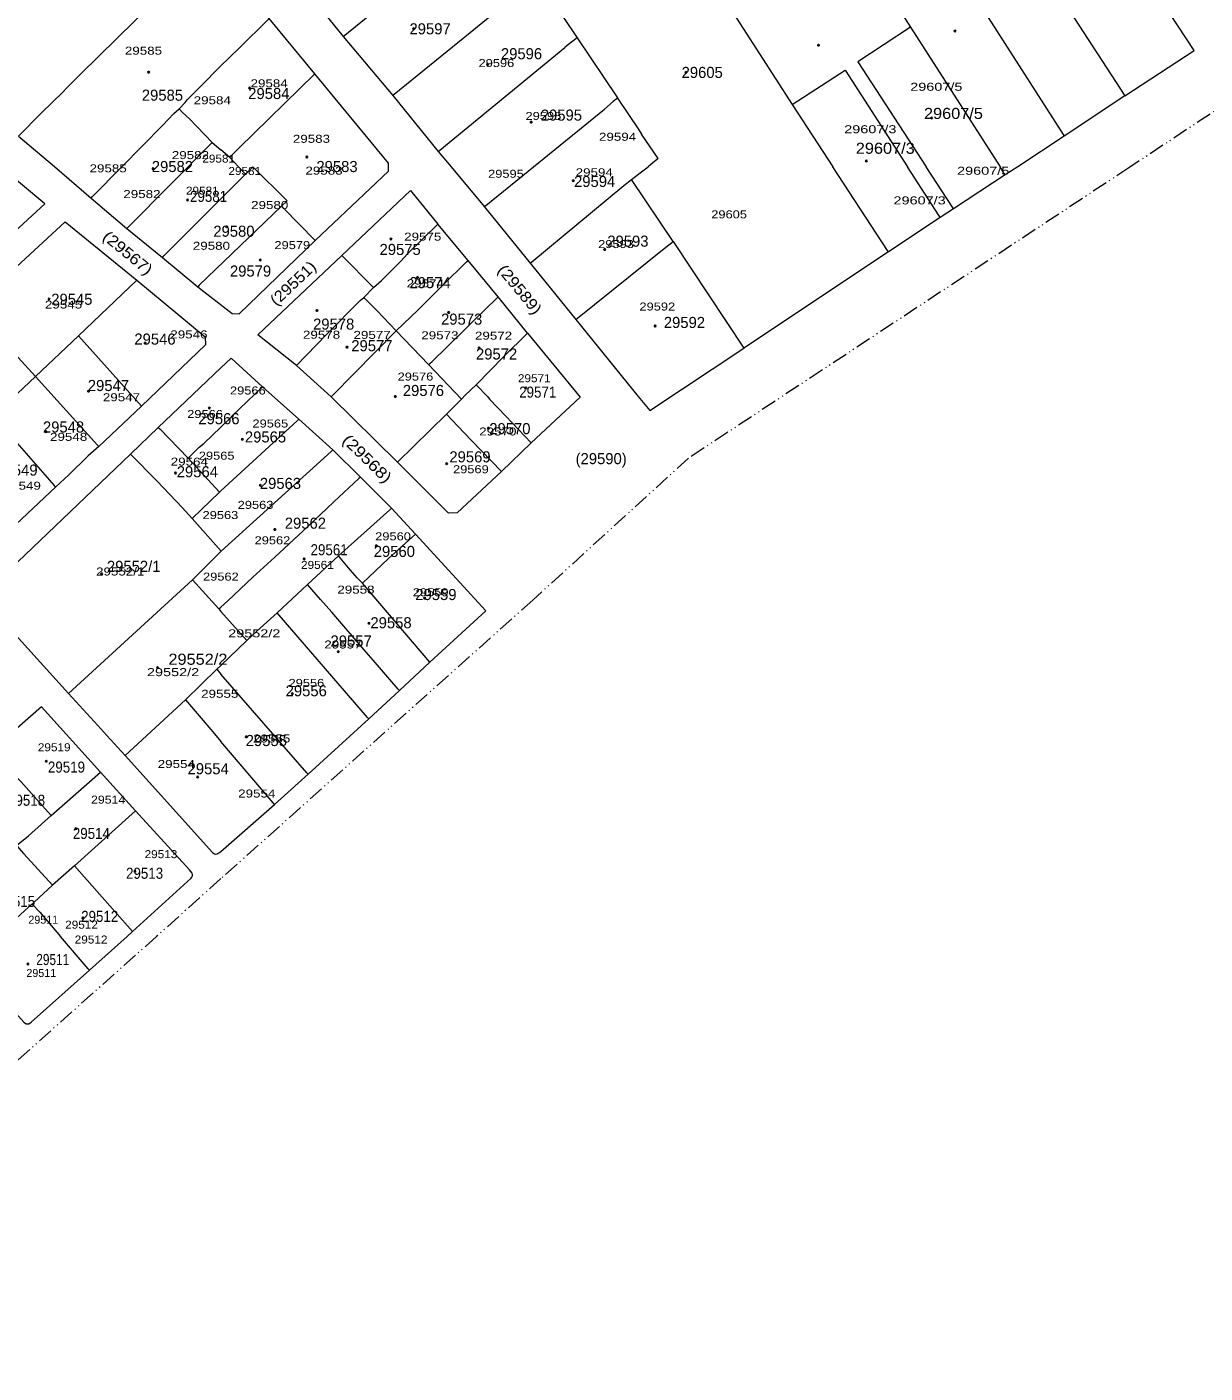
# Model space of a CAD drawing. Extents: x 650553 to 652508, y 239277 to 241647.
# Drawn here: x 651687 to 652069.7, y 240108.2 to 240545.4 of the extents above; entities that cross this region are included whole.
import ezdxf

# ---------------------------------------------------------------- set-up
doc = ezdxf.new("R2010")
doc.units = 0
doc.header["$PDMODE"] = 32
doc.header["$PDSIZE"] = 0.5
doc.linetypes.add('DASH_DOUBLE_DOT', pattern=[9.2, 5, -1.2, 0.3, -1.2, 0.3, -1.2])
for name, color, linetype in [('19', 7, 'Continuous'), ('20', 7, 'Continuous'), ('6', 7, 'Continuous')]:
    doc.layers.add(name, color=color, linetype=linetype)
for name, color, linetype, lineweight in [('3', 7, 'Continuous', 13), ('5', 7, 'Continuous', 13), ('52', 7, 'DASH_DOUBLE_DOT', 13)]:
    doc.layers.add(name, color=color, linetype=linetype, lineweight=lineweight)

msp = doc.modelspace()

# ---------------------------------------------------------------- linework, layer by layer
at = {"layer": '3'}
for p, q in [((651767.56, 240569.86), (651789.69, 240542.31)), ((652043.65, 240523), (652023.98, 240509.93)), ((651684.3, 240509.906), (651695.95, 240500.024)), ((651724.23, 240422.23), (651710.36, 240409.09)), ((651850.85, 240410.31), (651841.15, 240401)), ((651722.28, 240290.75), (651710.91, 240303.32)), ((651719.59, 240250), (651721.36, 240251.59))]:
    msp.add_line(p, q, dxfattribs=at)
for points in [[(651780.52, 240530.19), (651765.75, 240548.18), (651746.79, 240571.618), (651732.727, 240588.221)], [(652043.65, 240523), (652066.18, 240537.76), (652044.73, 240570.4)], [(651789.69, 240542.31), (651805.84, 240523.13), (651820.65, 240504.98)], [(651804.45, 240500), (651804.45, 240501.19), (651780.52, 240530.19)], [(652023.98, 240509.93), (652008.87, 240500), (652004.81, 240497.33), (651987.98, 240486.35), (651983.63, 240483.5), (651966.92, 240472.32), (651919.93, 240441.02)], [(651820.65, 240504.98), (651824.79, 240500), (651835.56, 240487.04), (651850.53, 240468.67), (651865.3, 240450.39), (651885.61, 240425.39)], [(651663.39, 240460.86), (651692.85, 240487.99), (651678.359, 240500.061)], [(651695.95, 240500.024), (651707.87, 240489.81), (651719.52, 240479.93), (651731.01, 240470.55), (651742.5, 240461.01)], [(651780.66, 240476.08), (651804.47, 240498.52), (651804.45, 240500)], [(651789.33, 240471.16), (651811.66, 240492.25), (651820.54, 240481.33)], [(651669.2, 240454.26), (651699.46, 240482.11), (651722.72, 240463.16)], [(651849.61, 240445.97), (651840.11, 240457.74), (651830.34, 240469.59), (651820.54, 240481.33)], [(651742.5, 240461.01), (651753.65, 240452.29), (651756.01, 240452.18), (651780.66, 240476.08)], [(651774.56, 240435.44), (651762.01, 240445.38), (651789.33, 240471.16)], [(651722.72, 240463.16), (651744.92, 240444.79), (651744.98, 240442.12), (651724.23, 240422.23)], [(651849.61, 240445.97), (651866.68, 240425.17), (651850.85, 240410.31)], [(651885.61, 240425.39), (651889.37, 240420.83), (651919.93, 240441.02)], [(651750, 240434.68), (651729.69, 240415.34), (651720.7, 240406.67)], [(651763.58, 240428.56), (651753.33, 240437.86), (651750, 240434.68)], [(651807.41, 240404.07), (651785.84, 240425.28), (651774.56, 240435.44)], [(651813.22, 240380.63), (651805.4, 240389.06), (651795.36, 240399.17), (651786.35, 240408), (651775.3, 240417.97), (651763.58, 240428.56)], [(651710.36, 240409.09), (651706.92, 240406.06), (651700.64, 240399.96), (651696.36, 240396.01), (651679.69, 240380.29)], [(651720.7, 240406.67), (651674.14, 240362.26), (651673.98, 240358.14), (651700.53, 240328.88)], [(651841.15, 240401), (651826.77, 240387.55), (651823.95, 240387.46), (651807.41, 240404.07)], [(651817.87, 240339.13), (651836.06, 240355.81), (651813.22, 240380.63)], [(651750, 240277.62), (651767.42, 240292.88), (651778.34, 240302.68), (651798.1, 240320.64), (651808.08, 240329.84), (651817.87, 240339.13)], [(651700.53, 240328.88), (651710.1, 240318.49), (651712.98, 240315.31), (651718.89, 240308.77)], [(651710.91, 240303.32), (651691.72, 240324.58), (651675.65, 240310.46)], [(651718.89, 240308.77), (651747.35, 240277.24), (651747.94, 240276.81), (651748.25, 240276.7), (651748.79, 240276.79), (651749.35, 240277.14), (651749.7, 240277.36), (651750, 240277.62)], [(651721.36, 240251.59), (651740.36, 240268.94), (651740.59, 240269.23), (651740.69, 240269.43), (651740.78, 240269.74), (651740.77, 240270.12), (651740.67, 240270.56), (651740.27, 240271.08), (651739.83, 240271.59), (651722.28, 240290.75)], [(651668.16, 240242.04), (651686.05, 240222.11), (651686.75, 240221.63), (651687.63, 240221.63), (651688.38, 240222.12), (651707.38, 240239.01), (651719.59, 240250)]]:
    msp.add_lwpolyline(points, dxfattribs=at)
at = {"layer": '5'}
for p, q in [((651952.88, 240578.32), (651974, 240545.35)), ((651789.69, 240542.31), (651814.44, 240562.63)), ((652022.45, 240555.62), (652043.65, 240523)), ((651974, 240545.35), (652003.1, 240500)), ((651865.79, 240541.92), (651878.88, 240522.33)), ((651878.854, 240522.308), (651885.76, 240512.02)), ((651851.53, 240500), (651874.65, 240518.75)), ((651885.76, 240512.02), (651886.65, 240510.58)), ((651892.03, 240502.7), (651886.65, 240510.58)), ((651752.92, 240503), (651750, 240505.47)), ((651752.92, 240503), (651755.74, 240500)), ((651865.3, 240450.39), (651894.58, 240473.92)), ((651896.95, 240475.71), (651919.93, 240441.02)), ((651703.75, 240445.08), (651722.72, 240463.16)), ((651740.68, 240385.76), (651750.108, 240375.13)), ((651749.33, 240356.36), (651750, 240356.95)), ((651758.4, 240346.09), (651750, 240355.59)), ((651748.66, 240336.76), (651750, 240335.23))]:
    msp.add_line(p, q, dxfattribs=at)
for points in [[(651973.9, 240588.07), (652023.66, 240510.43), (652023.98, 240509.93)], [(651903.75, 240569.66), (651935.56, 240520.19), (651948.78, 240500)], [(651684.3, 240509.906), (651691.776, 240517.523), (651698.788, 240524.311), (651699.785, 240525.447), (651704.534, 240530.177), (651722.068, 240547.369), (651727.626, 240552.993), (651733.93, 240559.128), (651737.908, 240563.103)], [(651831, 240543.63), (651833.38, 240545.52), (651846.72, 240556.46), (651852.61, 240561.44), (651865.79, 240541.92), (651862.49, 240539.35), (651861.77, 240538.68)], [(651765.75, 240548.18), (651765.25, 240547.685), (651756.07, 240538.6), (651749.902, 240532.663)], [(651974, 240545.35), (651956.96, 240534.09), (651979.11, 240500)], [(651805.84, 240523.13), (651806.34, 240523.537), (651831, 240543.63)], [(651820.65, 240504.98), (651821.15, 240505.39), (651861.77, 240538.68)], [(651717.88, 240500), (651731.008, 240513.379), (651734.733, 240517.238), (651736.464, 240518.811), (651738.371, 240520.83), (651739.09, 240521.71), (651743.385, 240526.043), (651749.902, 240532.663)], [(651935.56, 240520.19), (651952.8, 240531.41), (651973.01, 240500)], [(651752.92, 240503), (651753.24, 240503.39), (651755.87, 240506.04), (651780.52, 240530.19)], [(651878.88, 240522.33), (651878.854, 240522.308), (651877.48, 240521.15), (651874.65, 240518.75)], [(651736.464, 240518.811), (651737.589, 240517.572), (651739.81, 240515.514), (651747.169, 240507.868), (651750, 240505.47)], [(651719.52, 240479.93), (651720.015, 240480.43), (651747.169, 240507.868)], [(651707.87, 240489.81), (651708.361, 240490.31), (651717.88, 240500)], [(651758.04, 240497.55), (651757.571, 240498.05), (651755.74, 240500)], [(651758.04, 240497.55), (651760.36, 240499.99), (651771.6, 240488.91), (651769.76, 240487.19)], [(651835.56, 240487.04), (651836.06, 240487.446), (651851.53, 240500)], [(651850.53, 240468.67), (651851.03, 240469.086), (651880.9, 240493.93), (651883.43, 240495.82), (651885.76, 240497.68), (651888.76, 240500)], [(651892.03, 240502.7), (651889.55, 240500.61), (651888.76, 240500)], [(651966.92, 240472.32), (651966.592, 240472.82), (651948.78, 240500)], [(651983.63, 240483.5), (651983.308, 240484), (651973.01, 240500)], [(651987.98, 240486.35), (651987.655, 240486.85), (651979.11, 240500)], [(652004.81, 240497.33), (652004.49, 240497.83), (652003.1, 240500)], [(651731.01, 240470.55), (651731.51, 240471.049), (651758.04, 240497.55)], [(651894.58, 240473.92), (651896.95, 240475.71), (651883.43, 240495.82)], [(651769.76, 240487.19), (651743, 240461.49), (651742.5, 240461.01)], [(651769.76, 240487.19), (651770.251, 240486.69), (651780.66, 240476.08)], [(651799.55, 240460.76), (651802.16, 240463.02), (651802.86, 240463.74), (651808.5, 240469.28), (651810.61, 240471.69), (651820.54, 240481.33)], [(651774.56, 240435.44), (651784.33, 240445.56), (651795.26, 240456.54), (651796.45, 240457.5), (651799.55, 240460.76), (651789.33, 240471.16)], [(651822.16, 240461.55), (651829.84, 240469.099), (651830.34, 240469.59)], [(651806.92, 240446.7), (651814.06, 240453.48), (651819.13, 240458.47), (651822.16, 240461.55)], [(651785.84, 240425.28), (651786.332, 240425.78), (651806.92, 240446.7), (651800.82, 240453.17), (651796.45, 240457.5)], [(651831.81, 240449.76), (651839.61, 240457.259), (651840.11, 240457.74)], [(651669.2, 240454.26), (651689.84, 240431.91), (651676.1, 240418.98)], [(651817.47, 240435.75), (651818.5, 240436.62), (651829.03, 240446.97), (651831.81, 240449.76)], [(651689.84, 240431.91), (651703.75, 240445.08), (651724.23, 240422.23)], [(651807.41, 240404.07), (651823.29, 240419.61), (651828.2, 240424.54), (651817.47, 240435.75), (651806.92, 240446.7)], [(651828.2, 240424.54), (651829.4, 240425.82), (651832.9, 240429.2), (651837.5, 240433.81), (651841.84, 240438.26), (651849.61, 240445.97)], [(651689.84, 240431.91), (651709.91, 240409.59), (651710.36, 240409.09)], [(651763.58, 240428.56), (651753.53, 240418.94), (651753.16, 240418.47), (651750, 240415.45)], [(651832.9, 240429.2), (651836.72, 240425.27), (651837.32, 240424.47), (651842.59, 240418.97), (651850.85, 240410.31)], [(651676.1, 240418.98), (651695.919, 240396.51), (651696.36, 240396.01)], [(651775.3, 240417.97), (651774.8, 240417.51), (651750, 240394.7)], [(651823.29, 240419.61), (651826.98, 240415.73), (651831.47, 240411.08), (651841.15, 240401)], [(651729.69, 240415.34), (651730.177, 240414.84), (651739.42, 240405.35), (651749.62, 240394.35), (651750, 240394.7)], [(651739.42, 240405.35), (651742.95, 240408.96), (651744.45, 240410.16), (651750, 240415.45)], [(651720.7, 240406.67), (651729.37, 240397.82), (651737.47, 240389.28), (651740.68, 240385.76), (651749.62, 240394.35)], [(651786.35, 240408), (651785.85, 240407.547), (651750.108, 240375.13)], [(651795.36, 240399.17), (651794.86, 240398.71), (651786.67, 240391.17), (651784.48, 240389.04), (651776.76, 240381.76), (651767.59, 240373.22), (651760.41, 240366.68), (651752.33, 240359.03), (651750, 240356.95)], [(651805.4, 240389.06), (651804.9, 240388.609), (651788.24, 240373.59), (651778.18, 240364.32), (651768.32, 240355.07), (651761.69, 240349.11), (651758.4, 240346.09), (651750, 240338.04)], [(651817.87, 240339.13), (651795.98, 240364.7), (651804.49, 240372.71), (651813.22, 240380.63)], [(651700.53, 240328.88), (651740.82, 240365.88), (651750.108, 240375.13)], [(651795.98, 240364.7), (651794.3, 240366.52), (651792.14, 240368.99), (651791.45, 240369.7), (651788.24, 240373.59)], [(651740.82, 240365.88), (651749.33, 240356.36), (651750, 240355.59)], [(651808.08, 240329.84), (651807.643, 240330.34), (651799.44, 240339.72), (651797.23, 240342.29), (651786.04, 240355.28), (651782.4, 240359.43), (651778.18, 240364.32)], [(651798.1, 240320.64), (651797.668, 240321.14), (651768.32, 240355.07)], [(651718.89, 240308.77), (651738.52, 240326.9), (651748.66, 240336.76), (651750, 240338.04)], [(651778.34, 240302.68), (651777.905, 240303.18), (651750, 240335.23)], [(651738.52, 240326.9), (651747.42, 240316.41), (651750, 240313.37)], [(651767.42, 240292.88), (651766.995, 240293.38), (651750, 240313.37)], [(651675.65, 240310.46), (651684.01, 240301.45), (651685.08, 240300.35), (651690.2, 240294.5), (651694.89, 240289.25), (651710.91, 240303.32)], [(651722.28, 240290.75), (651702.45, 240272.91), (651721.36, 240251.59)], [(651683.68, 240279.53), (651687.51, 240282.73), (651694.89, 240289.25)], [(651683.68, 240279.53), (651686.05, 240276.8), (651695.36, 240266.66)], [(651702.45, 240272.91), (651695.36, 240266.66), (651689.41, 240261.12)], [(651689.41, 240261.12), (651688.7, 240260.49), (651687.5, 240259.47), (651676.99, 240250)], [(651688.7, 240260.49), (651691.25, 240257.87), (651697.98, 240250)], [(651707.38, 240239.01), (651706.952, 240239.51), (651697.98, 240250)]]:
    msp.add_lwpolyline(points, dxfattribs=at)
at = {"layer": '52'}
for points in [[(652125.045, 240552.683), (652045.248, 240499.833), (651901.888, 240405.32), (651851.361, 240359.263), (651750.052, 240268.782)], [(651750.052, 240268.782), (651729.12, 240250.009), (651567.141, 240105.534), (651448.015, 239999.895)]]:
    msp.add_lwpolyline(points, dxfattribs=at)
at = {"layer": '6'}
for p in [(651812.617, 240544.815), (651988.47, 240544.055), (651944.13, 240539.465), (651726.533, 240530.714), (651836.654, 240533.21), (651901.081, 240530.645), (651759.38, 240525.59), (651850.813, 240514.48), (651980.87, 240515.85), (651777.938, 240503.135), (651959.684, 240501.865), (651728.01, 240499.37), (651864.479, 240495.489), (651739.197, 240489.209), (651751.883, 240480.5), (651805.28, 240476.505), (651762.799, 240469.685), (651874.714, 240473.105), (651813.904, 240464.015), (651694.228, 240457.01), (651781.219, 240453.3), (651824.022, 240452.67), (651891.075, 240448.27), (651725.427, 240442.695), (651790.999, 240441.39), (651833.921, 240441.14), (651707.029, 240427.085), (651849.086, 240428.14), (651746.292, 240421.605), (651806.667, 240425.385), (651693.254, 240413.96), (651836.935, 240415.1), (651757.013, 240411.455), (651735.283, 240400.55), (651823.329, 240403.535), (651762.868, 240396.55), (651767.543, 240382.18), (651800.488, 240376.88), (651777.07, 240372.63), (651711.322, 240367.775), (651816.21, 240359.88), (651798.104, 240351.715), (651788.138, 240342.48), (651729.489, 240337.325), (651773.255, 240328.875), (651758.27, 240314.82), (651693.302, 240306.915), (651742.509, 240301.8), (651702.973, 240284.99), (651722.093, 240271.17), (651705.184, 240255.96), (651687.333, 240241.06)]:
    msp.add_point(p, dxfattribs=at)

# ---------------------------------------------------------------- texts
at = {"layer": '19'}
for s, p in [('29597', (651811.279, 240542.993)), ('29596', (651840.977, 240534.91)), ('29605', (651899.668, 240528.835)), ('29585', (651724.344, 240521.44)), ('29584', (651758.901, 240521.978)), ('29595', (651853.936, 240514.974)), ('29582', (651727.584, 240498.27)), ('29583', (651781.041, 240498.27)), ('29594', (651864.735, 240493.421)), ('29580', (651747.562, 240477.256)), ('29575', (651801.56, 240471.329)), ('29593', (651875.534, 240474.023)), ('29579', (651752.961, 240464.324)), ('29574', (651811.28, 240460.552)), ('29545', (651694.92, 240455.163)), ('29573', (651821.539, 240448.698)), ('29578', (651779.962, 240447.082)), ('29592', (651893.893, 240447.621)), ('29546', (651721.919, 240442.231)), ('29577', (651792.381, 240440.077)), ('29572', (651832.878, 240437.383)), ('29547', (651706.8, 240427.144)), ('29576', (651809.12, 240425.529)), ('29548', (651692.22, 240413.673)), ('29566', (651742.703, 240416.369)), ('29565', (651757.821, 240410.442)), ('29570', (651837.198, 240413.136)), ('29569', (651824.238, 240403.976)), ('(29590)', (651865.25, 240403.391)), ('29549', (651677.102, 240399.664)), ('29564', (651735.683, 240399.127)), ('29563', (651762.681, 240395.355)), ('29562', (651770.78, 240382.423)), ('29560', (651799.675, 240373.261)), ('29552/1', (651713.005, 240368.413)), ('29559', (651813.173, 240359.252)), ('29558', (651798.594, 240350.092)), ('29557', (651785.635, 240344.165)), ('29556', (651771.056, 240328)), ('29555', (651758.097, 240311.835)), ('29554', (651739.197, 240302.675))]:
    msp.add_text(s, height=3.6, dxfattribs=at).set_placement(p)
for s, width, p in [('29607/5', 1.1, (651978.397, 240515.513)), ('29607/3', 1.1, (651956.258, 240504.198)), ('29581', 0.9, (651740.003, 240488.571)), ('29571', 0.9, (651846.917, 240424.99)), ('29561', 0.9, (651779.157, 240373.8)), ('29552/2', 1.1, (651732.982, 240338.239)), ('29519', 0.9, (651693.838, 240303.214)), ('29518', 0.9, (651680.879, 240292.438)), ('29514', 0.9, (651701.936, 240281.661)), ('29513', 0.9, (651719.216, 240268.729)), ('29515', 0.9, (651677.639, 240259.569)), ('29512', 0.9, (651704.637, 240254.72)), ('29511', 0.8, (651690.058, 240240.71))]:
    msp.add_text(s, height=3.6, dxfattribs=dict(at, width=width)).set_placement(p)
for s, rotation, width, p in [('(29567)', 320.446, 1.15, (651711.266, 240476.702)), ('(29551)', 43.339, 1.1, (651768.055, 240454.591)), ('(29589)', 309.505, 1.15, (651839.661, 240466.364)), ('(29568)', 315.578, 1.2, (651789.149, 240410.857))]:
    msp.add_text(s, height=3.6, rotation=rotation, dxfattribs=dict(at, width=width)).set_placement(p)
at = {"layer": '20'}
for s, width, p in [('29585', 1.25, (651718.84, 240536.396)), ('29596', 1.2, (651833.713, 240532.381)), ('29584', 1.25, (651759.659, 240525.79)), ('29607/5', 1.35, (651973.92, 240524.669)), ('29584', 1.25, (651741.194, 240520.284)), ('29595', 1.2, (651848.973, 240515.194)), ('29607/3', 1.35, (651952.484, 240510.879)), ('29583', 1.25, (651773.394, 240507.77)), ('29594', 1.25, (651872.829, 240508.432)), ('29582', 1.25, (651734.086, 240502.476)), ('29585', 1.25, (651707.366, 240498.18)), ('29581', 1.1, (651743.992, 240501.345)), ('29583', 1.25, (651777.485, 240497.441)), ('29607/5', 1.35, (651989.147, 240497.391)), ('29581', 1.1, (651752.466, 240497.327)), ('29595', 1.2, (651836.816, 240496.409)), ('29594', 1.25, (651865.254, 240496.895)), ('29582', 1.25, (651718.33, 240489.821)), ('29581', 1.1, (651738.677, 240490.936)), ('29580', 1.25, (651759.839, 240486.257)), ('29607/3', 1.35, (651968.493, 240487.766)), ('29605', 1.2, (651909.302, 240483.232)), ('29575', 1.25, (651809.553, 240475.996)), ('29580', 1.25, (651740.903, 240473.025)), ('29579', 1.2, (651767.415, 240473.246)), ('29593', 1.2, (651872.568, 240473.583)), ('29574', 1.25, (651810.377, 240460.816)), ('29545', 1.25, (651692.883, 240453.944)), ('29592', 1.2, (651885.981, 240453.291)), ('29546', 1.25, (651733.597, 240444.24)), ('29578', 1.25, (651776.679, 240444.136)), ('29577', 1.25, (651793.101, 240444.082)), ('29573', 1.25, (651815.119, 240443.952)), ('29572', 1.25, (651832.55, 240443.83)), ('29576', 1.2, (651807.42, 240430.554)), ('29571', 1.1, (651846.502, 240430.012)), ('29547', 1.25, (651711.686, 240423.833)), ('29566', 1.2, (651752.976, 240426.023)), ('29566', 1.2, (651739.084, 240418.385)), ('29565', 1.2, (651760.281, 240415.302)), ('29548', 1.25, (651694.53, 240410.972)), ('29570', 1.25, (651833.93, 240412.706)), ('29564', 1.25, (651733.728, 240402.916)), ('29565', 1.2, (651742.849, 240404.843)), ('29569', 1.2, (651825.428, 240400.442)), ('29549', 1.25, (651679.461, 240395.1)), ('29563', 1.2, (651755.485, 240388.88)), ('29563', 1.2, (651744.074, 240385.569)), ('29562', 1.2, (651760.968, 240377.361)), ('29560', 1.2, (651800.14, 240378.658)), ('29552/1', 1.25, (651709.475, 240367.233)), ('29561', 1.1, (651776.053, 240369.373)), ('29562', 1.2, (651744.228, 240365.569)), ('29558', 1.25, (651787.847, 240361.339)), ('29559', 1.2, (651812.357, 240360.489)), ('29552/2', 1.35, (651752.391, 240347.151)), ('29557', 1.25, (651783.615, 240343.526)), ('29552/2', 1.35, (651726.008, 240334.55)), ('29555', 1.25, (651743.608, 240327.518)), ('29556', 1.2, (651772.003, 240331.043)), ('29519', 1.1, (651690.565, 240310.15)), ('29555', 1.25, (651760.497, 240312.993)), ('29554', 1.25, (651729.503, 240304.705)), ('29514', 1.15, (651707.841, 240293.132)), ('29554', 1.25, (651755.639, 240295.121)), ('29513', 1.1, (651725.238, 240275.429)), ('29512', 1.1, (651699.445, 240252.521)), ('29512', 1.1, (651702.542, 240247.703))]:
    msp.add_text(s, height=2.6, dxfattribs=dict(at, width=width)).set_placement(p)
for p in [(651687.49, 240254.136), (651686.853, 240236.835)]:
    msp.add_text('29511', height=2.6, dxfattribs=at).set_placement(p)

doc.saveas('drawing.dxf')
